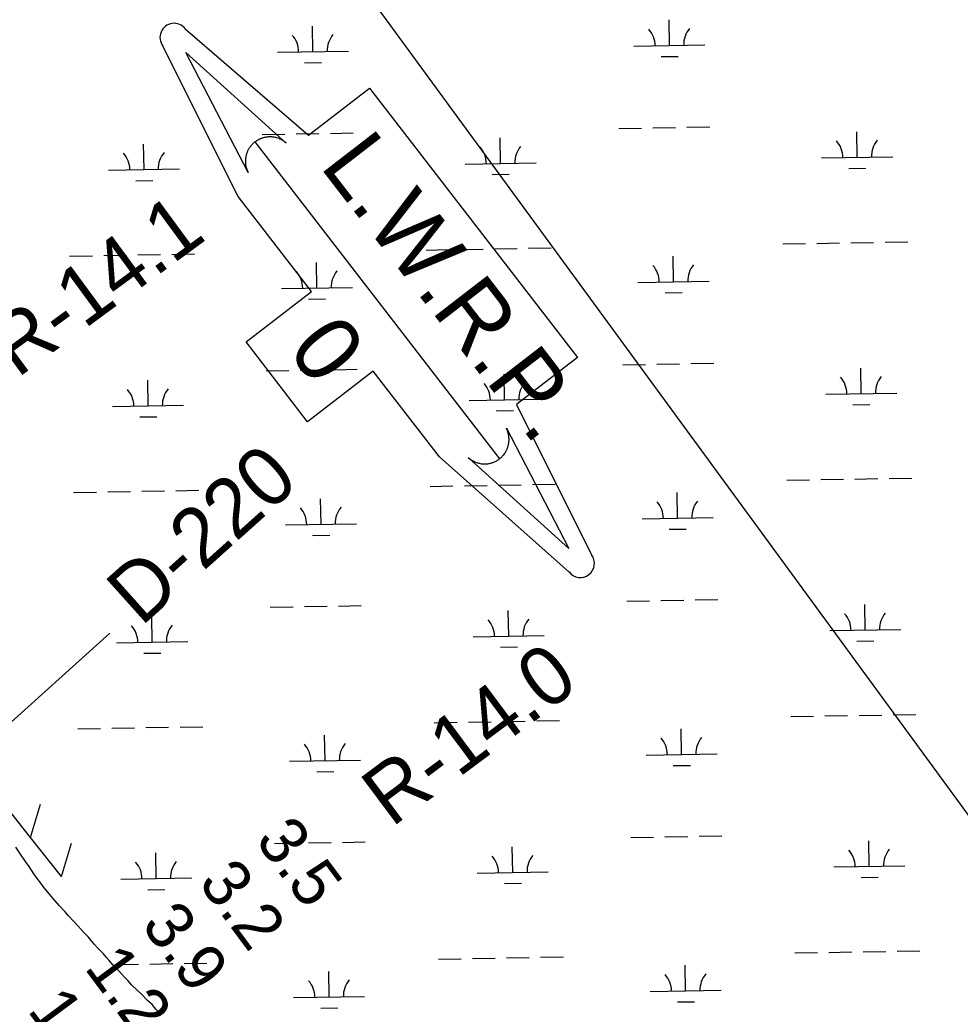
# Model space of a CAD drawing. Extents: x 3887375 to 3925618, y 296674 to 322633.
# Drawn here: x 3904521 to 3905845, y 303211 to 304610 of the extents above; entities that cross this region are included whole.
import ezdxf

# ---------------------------------------------------------------- set-up
doc = ezdxf.new("R2010")
doc.units = 0
for name, color, linetype in [('V-RIVR-EDGE', 7, 'Continuous'), ('V-RIVR-RANG', 7, 'Continuous'), ('V-RIVR-RANG-IDEN', 7, 'Continuous'), ('V-RRAP-FSHR', 7, 'Continuous'), ('V-TOPO-WATR-IDEN', 7, 'Continuous'), ('V-UTIL-LINE', 7, 'Continuous'), ('V-WETL-SWMP', 7, 'Continuous')]:
    doc.layers.add(name, color=color, linetype=linetype)

msp = doc.modelspace()

# ---------------------------------------------------------------- linework, layer by layer
at = {"layer": 'V-RIVR-EDGE'}
msp.add_spline([(3903770.8, 304167), (3903771.4, 304174.6), (3903768.5, 304179.6), (3903762.5, 304179.3), (3903755.1, 304174.6), (3903752.1, 304164.7), (3903751.5, 304159), (3903754.8, 304151.4), (3903758.4, 304144.7), (3903757, 304137.4), (3903757, 304131.1), (3903762.3, 304125.4), (3903773.6, 304116.4), (3903785.6, 304106.1), (3903792.2, 304094.1), (3903793.5, 304088.8), (3903799.5, 304081.8), (3903811.4, 304070.8), (3903831.3, 304054.7), (3903842.3, 304049.1), (3903853.6, 304046.7), (3903858.3, 304053), (3903863.9, 304057.3), (3903875.9, 304060.3), (3903902.2, 304051.2), (3903921.7, 304037.9), (3903928.4, 304024.6), (3903933.7, 304014.9), (3903938.6, 304011.6), (3903950.6, 304007.9), (3903951.3, 304004.6), (3903936.6, 303996.3), (3903920, 303988), (3903913.3, 303987.4), (3903903.7, 303986.1), (3903899, 303985.4), (3903896, 303988.4), (3903894.7, 303993.7), (3903890.4, 303996.4), (3903886.4, 303993.4), (3903885, 303990.4), (3903885.4, 303984.8), (3903888, 303978.4), (3903902.9, 303962.1), (3903914.5, 303946.8), (3903923.5, 303944.4), (3903940.8, 303941.1), (3903950.1, 303937.7), (3903959.7, 303925.4), (3903966.3, 303909.8), (3903971.2, 303869.5), (3903974.8, 303858.9), (3903983.5, 303847.2), (3904004, 303830.5), (3904027.9, 303812.2), (3904040.9, 303805.5), (3904046.2, 303808.1), (3904059.2, 303805.4), (3904061.5, 303801.4), (3904072.1, 303774.5), (3904080.3, 303764.5), (3904085.7, 303761.8), (3904095.6, 303758.8), (3904101.9, 303751.5), (3904110.9, 303736.5), (3904111.8, 303719.2), (3904112.8, 303710.5), (3904123.4, 303704.5), (3904134.1, 303703.5), (3904145.7, 303701.5), (3904155.7, 303704.4), (3904162.7, 303703.8), (3904166, 303699.1), (3904166, 303693.8), (3904159, 303685.1), (3904146.3, 303676.9), (3904141, 303675.5), (3904131, 303680.2), (3904126.7, 303681.2), (3904126, 303679.2), (3904131.3, 303669.6), (3904135.9, 303648), (3904141.9, 303635), (3904147.5, 303628.3), (3904153.8, 303623.3), (3904159.5, 303621.6), (3904161.8, 303617.6), (3904170, 303592), (3904172.4, 303588.3), (3904176.3, 303587.7), (3904179.3, 303587.7), (3904182.7, 303583.7), (3904192.9, 303568), (3904202.2, 303556.3), (3904216.1, 303544), (3904230.8, 303534), (3904242.4, 303528), (3904251.3, 303516.3), (3904260.3, 303502), (3904274.8, 303473.4), (3904284.1, 303457.7), (3904300.4, 303440.4), (3904316.2, 303412.7), (3904327.5, 303389.4), (3904354, 303350.8), (3904376.9, 303327.5), (3904388.1, 303308.2), (3904408.4, 303282.2), (3904417, 303276.2), (3904425.9, 303261.5), (3904434.9, 303242.2), (3904460.1, 303210.5), (3904493.5, 303168.2), (3904499.5, 303156.2), (3904515.4, 303136.2), (3904535.3, 303109.9), (3904550.9, 303088.9), (3904578.1, 303056), (3904601.9, 303022), (3904623.1, 302991.7), (3904644, 302960.4), (3904673.8, 302922.4), (3904699.4, 302886.1), (3904723.2, 302853.7), (3904742.4, 302827.4), (3904786.2, 302772.8), (3904807.1, 302745.5), (3904837.2, 302707.5), (3904854.8, 302680.5), (3904867.1, 302662.5), (3904915.8, 302598.2), (3904946.6, 302556.9), (3904978.4, 302512.3), (3905022.2, 302457.3), (3905048.4, 302422.6), (3905069.2, 302392.3), (3905083.5, 302372.7), (3905098, 302354.4)], degree=3, dxfattribs=at)
at = {"layer": 'V-RIVR-RANG'}
msp.add_line((3904647.8, 303747), (3904127.6, 303278.7), dxfattribs=at)
at = {"layer": 'V-RRAP-FSHR'}
for p, q in [((3904536.3, 303459.5), (3904550.2, 303506.3)), ((3904579.8, 303404.7), (3904593.7, 303451.5))]:
    msp.add_line(p, q, dxfattribs=at)
for points in [[(3904536.3, 303459.5), (3904492.7, 303514.3)], [(3904579.8, 303404.7), (3904536.3, 303459.5)]]:
    msp.add_lwpolyline(points, dxfattribs=at)
at = {"layer": 'V-TOPO-WATR-IDEN'}
msp.add_line((3904852, 304438.3), (3905196.4, 303992.4), dxfattribs=at)
for points in [[(3904754, 304597.6), (3904927.3, 304447.7), (3905013.2, 304514.1), (3905305.9, 304135.1), (3905220, 304068.7), (3905325.8, 303857.3)], [(3905294.3, 303833), (3905111.6, 303995), (3905018.4, 304115.8), (3904926.2, 304044.6), (3904839.5, 304156.8), (3904931.7, 304228), (3904828.6, 304361.5), (3904722.6, 304573.3)]]:
    msp.add_lwpolyline(points, dxfattribs=at)
for points in [[(3904842.5, 304395.4), (3904754.6, 304564.3), (3904895.9, 304436.6), (3904893.2, 304438.8), (3904890.5, 304440.6), (3904889.3, 304441.3), (3904888.3, 304441.8), (3904887, 304442.4), (3904885.7, 304443), (3904884.6, 304443.4), (3904883.1, 304443.9), (3904881.4, 304444.4), (3904880.4, 304444.6), (3904879.2, 304444.8), (3904877.5, 304445.1), (3904876.3, 304445.3), (3904874.9, 304445.4), (3904874, 304445.4), (3904873, 304445.4), (3904871.7, 304445.4), (3904870.6, 304445.3), (3904869.5, 304445.2), (3904868.6, 304445.1), (3904867.2, 304444.9), (3904865.9, 304444.7), (3904864.9, 304444.5), (3904863.7, 304444.1), (3904862.7, 304443.8), (3904861.8, 304443.5), (3904861.1, 304443.3), (3904860, 304442.9), (3904858.9, 304442.4), (3904857.9, 304442), (3904856.9, 304441.5), (3904856, 304441), (3904855.1, 304440.4), (3904854.3, 304439.9), (3904853.2, 304439.1), (3904852, 304438.3), (3904851.6, 304438), (3904851.1, 304437.5), (3904850.4, 304437), (3904849.8, 304436.5), (3904849.3, 304435.9), (3904848.7, 304435.4), (3904848.1, 304434.8), (3904847.7, 304434.3), (3904847.1, 304433.6), (3904846.5, 304433), (3904846.1, 304432.5), (3904845.2, 304431.3), (3904844.8, 304430.7), (3904844.4, 304430.2), (3904843.9, 304429.4), (3904843.5, 304428.7), (3904843.1, 304428), (3904842.6, 304427.1), (3904842.2, 304426.3), (3904841.8, 304425.6), (3904841.6, 304425), (3904841.2, 304424.2), (3904841, 304423.5), (3904840.6, 304422.7), (3904840.4, 304421.8), (3904840.1, 304421), (3904839.8, 304419.8), (3904839.6, 304419), (3904839.4, 304418.1), (3904839.2, 304417.2), (3904839.1, 304416.5), (3904838.9, 304415.7), (3904838.8, 304414.6), (3904838.8, 304414.5), (3904838.7, 304413.8), (3904838.7, 304413.3), (3904838.7, 304412.5), (3904838.6, 304411.6), (3904838.6, 304410.8), (3904838.6, 304410.1), (3904838.7, 304409.2), (3904838.7, 304408.4), (3904838.8, 304407.8), (3904838.9, 304407), (3904839, 304405.9), (3904839.1, 304405.3), (3904839.2, 304404.8), (3904839.3, 304404.3), (3904839.4, 304403.7), (3904839.6, 304403), (3904839.8, 304402.3), (3904840, 304401.6), (3904840.2, 304400.9), (3904840.5, 304400), (3904840.7, 304399.5), (3904841, 304398.7), (3904841.4, 304397.7), (3904841.7, 304397), (3904841.9, 304396.5), (3904842.1, 304396), (3904842.3, 304395.6)], [(3905205.9, 304035.3), (3905293.7, 303866.3), (3905152.4, 303994), (3905155.1, 303991.8), (3905157.9, 303990), (3905159, 303989.4), (3905160.1, 303988.8), (3905161.3, 303988.2), (3905162.6, 303987.7), (3905163.7, 303987.2), (3905165.3, 303986.7), (3905166.9, 303986.3), (3905167.9, 303986), (3905169.1, 303985.8), (3905170.8, 303985.5), (3905172.1, 303985.4), (3905173.4, 303985.3), (3905174.4, 303985.2), (3905175.4, 303985.2), (3905176.6, 303985.2), (3905177.7, 303985.3), (3905178.8, 303985.4), (3905179.8, 303985.5), (3905181.1, 303985.7), (3905182.4, 303985.9), (3905183.4, 303986.2), (3905184.6, 303986.5), (3905185.7, 303986.8), (3905186.6, 303987.1), (3905187.3, 303987.3), (3905188.3, 303987.7), (3905189.4, 303988.2), (3905190.4, 303988.7), (3905191.4, 303989.2), (3905192.3, 303989.7), (3905193.3, 303990.2), (3905194.1, 303990.7), (3905195.2, 303991.5), (3905196.4, 303992.4), (3905196.7, 303992.7), (3905197.3, 303993.1), (3905197.9, 303993.6), (3905198.5, 303994.2), (3905199.1, 303994.7), (3905199.6, 303995.2), (3905200.2, 303995.9), (3905200.7, 303996.3), (3905201.3, 303997), (3905201.8, 303997.6), (3905202.2, 303998.1), (3905203.1, 303999.3), (3905203.6, 304000), (3905203.9, 304000.4), (3905204.4, 304001.2), (3905204.8, 304001.9), (3905205.2, 304002.6), (3905205.7, 304003.5), (3905206.2, 304004.4), (3905206.5, 304005), (3905206.7, 304005.6), (3905207.1, 304006.4), (3905207.4, 304007.1), (3905207.7, 304007.9), (3905208, 304008.8), (3905208.2, 304009.7), (3905208.6, 304010.8), (3905208.8, 304011.6), (3905209, 304012.5), (3905209.1, 304013.4), (3905209.3, 304014.1), (3905209.4, 304014.9), (3905209.5, 304016.1), (3905209.5, 304016.1), (3905209.6, 304016.8), (3905209.6, 304017.3), (3905209.7, 304018.1), (3905209.7, 304019), (3905209.7, 304019.8), (3905209.7, 304020.5), (3905209.6, 304021.4), (3905209.6, 304022.2), (3905209.5, 304022.8), (3905209.4, 304023.6), (3905209.3, 304024.7), (3905209.2, 304025.4), (3905209.1, 304025.9), (3905209, 304026.3), (3905208.9, 304026.9), (3905208.7, 304027.6), (3905208.5, 304028.3), (3905208.4, 304029), (3905208.1, 304029.7), (3905207.9, 304030.6), (3905207.7, 304031.1), (3905207.4, 304032), (3905207, 304032.9), (3905206.7, 304033.6), (3905206.4, 304034.2), (3905206.2, 304034.7), (3905206, 304035)]]:
    msp.add_lwpolyline(points, close=True, dxfattribs=at)
for centre, start, end in [((3904738.3, 304585.4), 37.6802, 217.6802), ((3905310, 303845.2), 217.6802, 37.6802)]:
    msp.add_arc(centre, 19.9, start, end, dxfattribs=at)
at = {"layer": 'V-UTIL-LINE'}
msp.add_lwpolyline([(3891385.6, 317757.3), (3896110, 314731.3), (3903763.5, 306349.6), (3906680.6, 302364)], dxfattribs=at)
at = {"layer": 'V-WETL-SWMP'}
for p, q in [((3905435.5, 304574), (3905434.9, 304610)), ((3904933.7, 304565.4), (3904933, 304601.4)), ((3905385.5, 304573.2), (3905485.5, 304574.9)), ((3904883.7, 304564.6), (3904983.6, 304566.3)), ((3904921.9, 304549.8), (3904945.9, 304550.2)), ((3905423.8, 304558.4), (3905447.8, 304558.8)), ((3904862.2, 304448.7), (3904894.2, 304449.3)), ((3904910.2, 304449.6), (3904942.2, 304450.1)), ((3904958.2, 304450.4), (3904990.2, 304450.9)), ((3905364.1, 304457.3), (3905396.1, 304457.9)), ((3905412.1, 304458.2), (3905444.1, 304458.7)), ((3905460.1, 304459), (3905492.1, 304459.5)), ((3905699.7, 304416.7), (3905699, 304452.7)), ((3904696, 304399.4), (3904695.4, 304435.4)), ((3905197.8, 304408.1), (3905197.2, 304444.1)), ((3905147.8, 304407.2), (3905247.8, 304408.9)), ((3905649.7, 304415.8), (3905749.7, 304417.5)), ((3904646, 304398.6), (3904746, 304400.3)), ((3905186.1, 304392.4), (3905210.1, 304392.8)), ((3905687.9, 304401), (3905711.9, 304401.4)), ((3904684.3, 304383.8), (3904708.3, 304384.2)), ((3905594.9, 304294.8), (3905626.9, 304295.3)), ((3905642.9, 304295.6), (3905674.9, 304296.2)), ((3905690.9, 304296.4), (3905722.9, 304297)), ((3905738.9, 304297.3), (3905770.9, 304297.8)), ((3905093.1, 304286.2), (3905125.1, 304286.7)), ((3905141.1, 304287), (3905173.1, 304287.5)), ((3905189, 304287.8), (3905221, 304288.4)), ((3905237, 304288.6), (3905269, 304289.2)), ((3904591.2, 304277.6), (3904623.2, 304278.1)), ((3904639.2, 304278.4), (3904671.2, 304278.9)), ((3904687.2, 304279.2), (3904719.2, 304279.8)), ((3904735.2, 304280), (3904767.2, 304280.6)), ((3904939.4, 304232.8), (3904938.7, 304268.8)), ((3905441.2, 304241.4), (3905440.6, 304277.4)), ((3905391.2, 304240.5), (3905491.2, 304242.3)), ((3904889.4, 304231.9), (3904989.4, 304233.6)), ((3905429.5, 304225.8), (3905453.5, 304226.2)), ((3904927.6, 304217.1), (3904951.6, 304217.6)), ((3905465.8, 304126.4), (3905497.8, 304126.9)), ((3904867.9, 304116.1), (3904899.9, 304116.7)), ((3904915.9, 304116.9), (3904947.9, 304117.5)), ((3904963.9, 304117.8), (3904995.9, 304118.3)), ((3905369.8, 304124.7), (3905401.8, 304125.3)), ((3905417.8, 304125.5), (3905449.8, 304126.1)), ((3905705.4, 304084), (3905704.8, 304120)), ((3904701.7, 304066.8), (3904701.1, 304102.8)), ((3905203.5, 304075.4), (3905202.9, 304111.4)), ((3905655.4, 304083.2), (3905755.4, 304084.9)), ((3905153.5, 304074.6), (3905253.5, 304076.3)), ((3904651.7, 304066), (3904751.7, 304067.7)), ((3905191.8, 304059.8), (3905215.8, 304060.2)), ((3905693.6, 304068.4), (3905717.6, 304068.8)), ((3904690, 304051.2), (3904714, 304051.6)), ((3905600.6, 303962.2), (3905632.6, 303962.7)), ((3905648.6, 303963), (3905680.6, 303963.5)), ((3905696.6, 303963.8), (3905728.6, 303964.4)), ((3905744.6, 303964.6), (3905776.6, 303965.2)), ((3904596.9, 303944.9), (3904628.9, 303945.5)), ((3904644.9, 303945.8), (3904676.9, 303946.3)), ((3904692.9, 303946.6), (3904724.9, 303947.1)), ((3904740.9, 303947.4), (3904772.9, 303948)), ((3905098.8, 303953.5), (3905130.8, 303954.1)), ((3905146.8, 303954.4), (3905178.8, 303954.9)), ((3905194.8, 303955.2), (3905226.8, 303955.7)), ((3905242.8, 303956), (3905274.7, 303956.6)), ((3904945.1, 303900.2), (3904944.5, 303936.2)), ((3905446.9, 303908.8), (3905446.3, 303944.8)), ((3905396.9, 303907.9), (3905496.9, 303909.6)), ((3904895.1, 303899.3), (3904995.1, 303901)), ((3905435.2, 303893.1), (3905459.2, 303893.5)), ((3904933.3, 303884.5), (3904957.3, 303884.9)), ((3905375.5, 303792.1), (3905407.5, 303792.6)), ((3905423.5, 303792.9), (3905455.5, 303793.5)), ((3905471.5, 303793.7), (3905503.5, 303794.3)), ((3904873.7, 303783.5), (3904905.7, 303784)), ((3904921.7, 303784.3), (3904953.6, 303784.9)), ((3904969.6, 303785.1), (3905001.6, 303785.7)), ((3905209.3, 303742.8), (3905208.6, 303778.8)), ((3905711.1, 303751.4), (3905710.5, 303787.4)), ((3904707.4, 303734.2), (3904706.8, 303770.2)), ((3905661.1, 303750.6), (3905761.1, 303752.3)), ((3904657.4, 303733.3), (3904757.4, 303735.1)), ((3905159.3, 303741.9), (3905259.2, 303743.7)), ((3905699.4, 303735.8), (3905723.3, 303736.2)), ((3905197.5, 303727.2), (3905221.5, 303727.6)), ((3904695.7, 303718.6), (3904719.7, 303719)), ((3905200.5, 303622.6), (3905232.5, 303623.1)), ((3905248.5, 303623.4), (3905280.5, 303623.9)), ((3905606.3, 303629.5), (3905638.3, 303630.1)), ((3905654.3, 303630.4), (3905686.3, 303630.9)), ((3905702.3, 303631.2), (3905734.3, 303631.7)), ((3905750.3, 303632), (3905782.3, 303632.6)), ((3904602.6, 303612.3), (3904634.6, 303612.9)), ((3904650.6, 303613.1), (3904682.6, 303613.7)), ((3904698.6, 303614), (3904730.6, 303614.5)), ((3904746.6, 303614.8), (3904778.6, 303615.3)), ((3905104.5, 303620.9), (3905136.5, 303621.5)), ((3905152.5, 303621.7), (3905184.5, 303622.3)), ((3905452.6, 303576.1), (3905452, 303612.1)), ((3904950.8, 303567.5), (3904950.2, 303603.5)), ((3904900.8, 303566.7), (3905000.8, 303568.4)), ((3905402.6, 303575.3), (3905502.6, 303577)), ((3905440.9, 303560.5), (3905464.9, 303560.9)), ((3904939.1, 303551.9), (3904963, 303552.3)), ((3905381.2, 303459.5), (3905413.2, 303460)), ((3905429.2, 303460.3), (3905461.2, 303460.8)), ((3905477.2, 303461.1), (3905509.2, 303461.7)), ((3904522.1, 303436.1), (3904515.4, 303445.7)), ((3904879.4, 303450.9), (3904911.4, 303451.4)), ((3904927.4, 303451.7), (3904959.4, 303452.2)), ((3904975.4, 303452.5), (3905007.3, 303453.1)), ((3905215, 303410.2), (3905214.3, 303446.2)), ((3905716.8, 303418.8), (3905716.2, 303454.8)), ((3904529.3, 303425.7), (3904522.1, 303436.1)), ((3904713.1, 303401.6), (3904712.5, 303437.6)), ((3904534.1, 303418.7), (3904529.3, 303425.7)), ((3904540.8, 303408.3), (3904534.1, 303418.7)), ((3905666.8, 303417.9), (3905766.8, 303419.7)), ((3904545.7, 303401.8), (3904540.8, 303408.3)), ((3904550.6, 303395.3), (3904545.7, 303401.8)), ((3904663.1, 303400.7), (3904763.1, 303402.4)), ((3905165, 303409.3), (3905265, 303411)), ((3905705.1, 303403.2), (3905729.1, 303403.6)), ((3904555.5, 303388.7), (3904550.6, 303395.3)), ((3904563.1, 303379.6), (3904555.5, 303388.7)), ((3904701.4, 303385.9), (3904725.4, 303386.3)), ((3905203.2, 303394.5), (3905227.2, 303395)), ((3904571.1, 303370.1), (3904563.1, 303379.6)), ((3904576.4, 303363.6), (3904571.1, 303370.1)), ((3904584.4, 303355.3), (3904576.4, 303363.6)), ((3904589.7, 303349.3), (3904584.4, 303355.3)), ((3904597.7, 303340.6), (3904589.7, 303349.3)), ((3904603.4, 303334.5), (3904597.7, 303340.6)), ((3904611.9, 303325), (3904603.4, 303334.5)), ((3904617.6, 303318.9), (3904611.9, 303325)), ((3904625.6, 303309.4), (3904617.6, 303318.9)), ((3904630.9, 303303.7), (3904625.6, 303309.4)), ((3904638.9, 303295.5), (3904630.9, 303303.7)), ((3904643.3, 303290.3), (3904638.9, 303295.5)), ((3904646.9, 303286.4), (3904643.3, 303290.3)), ((3905110.2, 303288.3), (3905142.2, 303288.8)), ((3905158.2, 303289.1), (3905190.2, 303289.7)), ((3905206.2, 303289.9), (3905238.2, 303290.5)), ((3905254.2, 303290.8), (3905286.2, 303291.3)), ((3905612, 303296.9), (3905644, 303297.5)), ((3905660, 303297.7), (3905692, 303298.3)), ((3905708, 303298.6), (3905740, 303299.1)), ((3905756, 303299.4), (3905788, 303299.9)), ((3904652.2, 303280.3), (3904646.9, 303286.4)), ((3904655.8, 303276.8), (3904652.2, 303280.3)), ((3904660.6, 303271.6), (3904655.8, 303276.8)), ((3904656.4, 303280.5), (3904688.3, 303281.1)), ((3904704.3, 303281.3), (3904736.3, 303281.9)), ((3904752.3, 303282.2), (3904784.3, 303282.7)), ((3905458.3, 303243.5), (3905457.7, 303279.5)), ((3904664.2, 303267.3), (3904660.6, 303271.6)), ((3904669.1, 303262.1), (3904664.2, 303267.3)), ((3904673.1, 303258.2), (3904669.1, 303262.1)), ((3904956.5, 303234.9), (3904955.9, 303270.9)), ((3904678.8, 303251.7), (3904673.1, 303258.2)), ((3904686.3, 303244.3), (3904678.8, 303251.7)), ((3904692.1, 303239.1), (3904686.3, 303244.3)), ((3904701, 303230), (3904692.1, 303239.1)), ((3904906.5, 303234), (3905006.5, 303235.8)), ((3905408.3, 303242.7), (3905508.3, 303244.4)), ((3904707.2, 303224.4), (3904701, 303230)), ((3904712.5, 303217.9), (3904707.2, 303224.4)), ((3904720, 303209.2), (3904712.5, 303217.9)), ((3904944.8, 303219.3), (3904968.8, 303219.7)), ((3905446.6, 303227.9), (3905470.6, 303228.3))]:
    msp.add_line(p, q, dxfattribs=at)
for centre, start, end in [((3904988.9, 304566.8), 140.2115, 181.7552), ((3905380.2, 304573.5), 0.2115, 41.7552), ((3905490.7, 304575.4), 140.2115, 181.7552), ((3904878.4, 304564.9), 0.2115, 41.7552), ((3905644.4, 304416.2), 0.2115, 41.7552), ((3905754.9, 304418.1), 140.2115, 181.7552), ((3904640.8, 304399), 0.2115, 41.7552), ((3904751.2, 304400.9), 140.2115, 181.7552), ((3905142.6, 304407.6), 0.2115, 41.7552), ((3905253.1, 304409.5), 140.2115, 181.7552), ((3904884.1, 304232.3), 0.2115, 41.7552), ((3904994.6, 304234.2), 140.2115, 181.7552), ((3905386, 304240.9), 0.2115, 41.7552), ((3905496.4, 304242.8), 140.2115, 181.7552), ((3905258.8, 304076.9), 140.2115, 181.7552), ((3905650.1, 304083.6), 0.2115, 41.7552), ((3905760.6, 304085.5), 140.2115, 181.7552), ((3904646.5, 304066.3), 0.2115, 41.7552), ((3904756.9, 304068.2), 140.2115, 181.7552), ((3905148.3, 304075), 0.2115, 41.7552), ((3905391.7, 303908.3), 0.2115, 41.7552), ((3905502.1, 303910.2), 140.2115, 181.7552), ((3904889.8, 303899.7), 0.2115, 41.7552), ((3905000.3, 303901.6), 140.2115, 181.7552), ((3905154, 303742.3), 0.2115, 41.7552), ((3905264.5, 303744.2), 140.2115, 181.7552), ((3905655.8, 303750.9), 0.2115, 41.7552), ((3905766.3, 303752.8), 140.2115, 181.7552), ((3904652.2, 303733.7), 0.2115, 41.7552), ((3904762.6, 303735.6), 140.2115, 181.7552), ((3905397.4, 303575.7), 0.2115, 41.7552), ((3905507.8, 303577.6), 140.2115, 181.7552), ((3904895.5, 303567.1), 0.2115, 41.7552), ((3905006, 303569), 140.2115, 181.7552), ((3905661.6, 303418.3), 0.2115, 41.7552), ((3905772, 303420.2), 140.2115, 181.7552), ((3905159.7, 303409.7), 0.2115, 41.7552), ((3905270.2, 303411.6), 140.2115, 181.7552), ((3904657.9, 303401.1), 0.2115, 41.7552), ((3904768.4, 303403), 140.2115, 181.7552), ((3905403.1, 303243), 0.2115, 41.7552), ((3905513.6, 303244.9), 140.2115, 181.7552), ((3904901.3, 303234.4), 0.2115, 41.7552), ((3905011.7, 303236.3), 140.2115, 181.7552)]:
    msp.add_arc(centre, 35.2, start, end, dxfattribs=at)

# ---------------------------------------------------------------- texts
at = {"layer": 'V-RIVR-RANG'}
for s, p in [('3.5', (3904851.2, 303455.5)), ('3.2', (3904771.1, 303395.7)), ('3.9', (3904690.8, 303336.1)), ('1.2', (3904610.8, 303276.1)), ('1.4', (3904530.7, 303216.2))]:
    msp.add_text(s, height=67, rotation=306.5983, dxfattribs=at).set_placement(p)
at = {"layer": 'V-RIVR-RANG-IDEN'}
for s, rotation, p in [('R-14.1', 36.3108, (3904517.5, 304105)), ('D-220', 41.8583, (3904691.7, 303755.2)), ('R-14.0', 36.7419, (3905044.3, 303472.6))]:
    msp.add_text(s, height=83, rotation=rotation, dxfattribs=at).set_placement(p)
at = {"layer": 'V-TOPO-WATR-IDEN'}
for s, height, rotation, p in [('L.W.R.P.', 93.37, 307.6801, (3904942.1, 304404.4)), ('0', 93.4, 307.6802, (3904896, 304145.7))]:
    msp.add_text(s, height=height, rotation=rotation, dxfattribs=at).set_placement(p)

doc.saveas('drawing.dxf')
